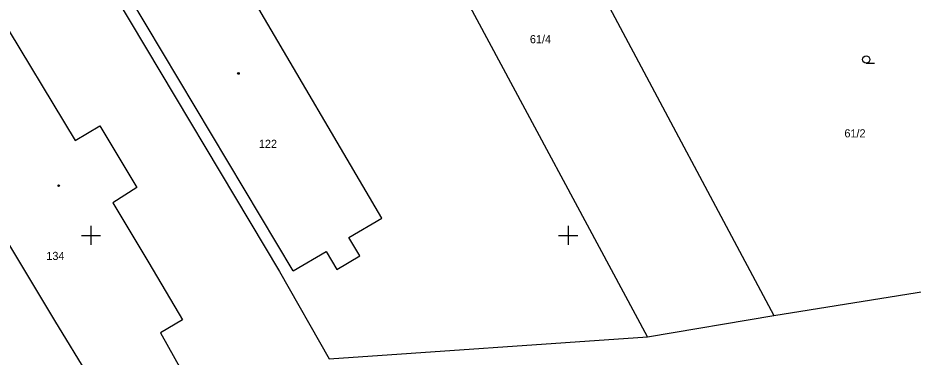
# Model space of a CAD drawing. Extents: x -703403 to -701924, y -1022520 to -1021856.
# Drawn here: x -703178.82 to -703131.93, y -1022131.38 to -1022113.61 of the extents above; entities that cross this region are included whole.
import ezdxf

# ---------------------------------------------------------------- set-up
doc = ezdxf.new("R2010")
doc.units = 0
for name, color, linetype in [('Z_hektometricka_sit', 7, 'Continuous'), ('Z_katastr_cisla_pozemkova', 7, 'Continuous'), ('Z_katastr_cisla_stavebni', 7, 'Continuous'), ('Z_katastr_hranice', 7, 'Continuous'), ('Z_katastr_vnitrni_kresba', 7, 'Continuous'), ('Z_katastr_znacky_budov', 7, 'Continuous'), ('Z_katastr_znacky_kultur', 7, 'Continuous')]:
    doc.layers.add(name, color=color, linetype=linetype)

msp = doc.modelspace()

# ---------------------------------------------------------------- linework, layer by layer
at = {"layer": 'Z_hektometricka_sit'}
for p, q in [((-703175, -1022124.5), (-703175, -1022125.5)), ((-703150, -1022124.5), (-703150, -1022125.5)), ((-703175.5, -1022125), (-703174.5, -1022125)), ((-703150.5, -1022125), (-703149.5, -1022125))]:
    msp.add_line(p, q, dxfattribs=at)
at = {"layer": 'Z_katastr_hranice'}
for p, q in [((-703145.85, -1022130.32), (-703161.23, -1022101.68)), ((-703150.46, -1022108.12), (-703139.23, -1022129.2)), ((-703175.35, -1022109.76), (-703165.12, -1022126.9)), ((-703185.18, -1022115.71), (-703176.91, -1022129.46)), ((-703165.12, -1022126.9), (-703162.52, -1022131.47)), ((-703139.23, -1022129.2), (-703126.06, -1022127.08)), ((-703176.91, -1022129.46), (-703174.73, -1022133)), ((-703145.85, -1022130.32), (-703139.23, -1022129.2)), ((-703162.52, -1022131.47), (-703145.85, -1022130.32))]:
    msp.add_line(p, q, dxfattribs=at)
at = {"layer": 'Z_katastr_vnitrni_kresba'}
for p, q in [((-703159.76, -1022124.1), (-703170.12, -1022106.48)), ((-703164.4, -1022126.86), (-703174.8, -1022109.44)), ((-703180.28, -1022112.67), (-703175.82, -1022120.04)), ((-703175.82, -1022120.04), (-703174.54, -1022119.27)), ((-703174.54, -1022119.27), (-703172.59, -1022122.49)), ((-703172.59, -1022122.49), (-703173.85, -1022123.29)), ((-703173.85, -1022123.29), (-703171.96, -1022126.44)), ((-703161.48, -1022125.12), (-703159.76, -1022124.1)), ((-703160.91, -1022126.07), (-703161.48, -1022125.12)), ((-703164.4, -1022126.86), (-703162.68, -1022125.84)), ((-703162.68, -1022125.84), (-703162.12, -1022126.78)), ((-703162.12, -1022126.78), (-703160.91, -1022126.07)), ((-703171.96, -1022126.44), (-703170.21, -1022129.42)), ((-703170.21, -1022129.42), (-703171.35, -1022130.11)), ((-703171.35, -1022130.11), (-703170.27, -1022132.04))]:
    msp.add_line(p, q, dxfattribs=at)
at = {"layer": 'Z_katastr_znacky_budov'}
for centre in [(-703167.272, -1022116.52), (-703176.692, -1022122.4)]:
    msp.add_circle(centre, 0.0437, dxfattribs=at)
at = {"layer": 'Z_katastr_znacky_kultur'}
msp.add_line((-703134.388, -1022115.98), (-703133.951, -1022115.98), dxfattribs=at)
msp.add_circle((-703134.388, -1022115.792), 0.187, dxfattribs=at)

# ---------------------------------------------------------------- texts
at = {"layer": 'Z_katastr_cisla_pozemkova'}
for s, p in [('61/4', (-703152.004, -1022114.94)), ('61/2', (-703135.529, -1022119.87))]:
    msp.add_text(s, height=0.425, dxfattribs=at).set_placement(p)
at = {"layer": 'Z_katastr_cisla_stavebni'}
for s, p in [('122', (-703166.199, -1022120.419)), ('134', (-703177.334, -1022126.289))]:
    msp.add_text(s, height=0.425, dxfattribs=at).set_placement(p)

doc.saveas('drawing.dxf')
